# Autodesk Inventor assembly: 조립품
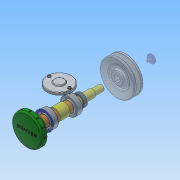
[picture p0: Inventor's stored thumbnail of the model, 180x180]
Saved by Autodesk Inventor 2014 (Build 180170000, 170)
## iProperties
Created: 2017-10
Part Number: 조립품
Document SubType Name: Assembly
Designer: NET
Author: NET
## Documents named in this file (20)
- C:\Users\NET\Desktop\471007V1039\조립품.iam
- C:\Users\NET\Desktop\471007V1039\본체.ipt
- C:\Users\NET\Desktop\471007V1039\사이드 커버.ipt
- 사이드 커버.ipt
- C:\Users\NET\Desktop\471007V1039\탑 커버.ipt
- C:\Users\NET\Desktop\471007V1039\와셔 3x6.ipt
- C:\Users\NET\Desktop\471007V1039\십자볼트 M3 x 10.ipt
- C:\Users\NET\Desktop\471007V1039\축.ipt
- C:\Users\NET\Desktop\471007V1039\너트 M10.ipt
- C:\Users\NET\Desktop\471007V1039\와셔 10x21.ipt
- C:\Users\NET\Desktop\471007V1039\부시2.ipt
- C:\Users\NET\Desktop\471007V1039\멈춤링 35x1.6.ipt
- C:\Users\NET\Desktop\471007V1039\베어링 15 x 35 x 11.ipt
- C:\Users\NET\Desktop\471007V1039\부시1.ipt
- C:\Users\NET\Desktop\471007V1039\멈춤링 15 x 1.ipt
- C:\Users\NET\Desktop\471007V1039\오일 실 15 25 7.ipt
- C:\Users\NET\Desktop\471007V1039\V-벨트풀리.ipt
- C:\Users\NET\Desktop\471007V1039\와셔 4x16.ipt
- C:\Users\NET\Desktop\471007V1039\볼트 M4 x 10.ipt
- C:\Users\NET\Desktop\471007V1039\키 4 x 4 x 18.ipt
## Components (2 placed, 2 different names)
1. V-벨트풀리:1 — 각도:1
2. ISO 4017 M4 x 10:1
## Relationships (1: Angle 1)
- 각도:1 [Angle]: V-벨트풀리:1
